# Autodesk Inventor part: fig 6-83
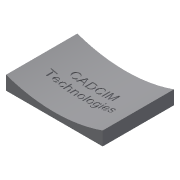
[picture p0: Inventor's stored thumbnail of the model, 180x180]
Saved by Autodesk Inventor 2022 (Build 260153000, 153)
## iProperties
Part Number: fig 6-83
Document SubType Name: Modeling
Created: 2002-12
Designer: deepak
Density: 1 g/cm^3
Material: Generic
Appearance: Default
Control State: 0
Master: False
Checked Out: False
Shininess: 64.0
Length Units: 11269
Angle Units: 11279
Time Units: 11290
Mass Units: 11283
Length Display Precision: 3
Angle Display Precision: 2
Compacted: True
Density: 0.0
Volumn: 0.0
Area: 0.0
PropertySet Name: Model Information
Author: deepak
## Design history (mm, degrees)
sketch "Sketch1"
  geometry: L1 (-39.922, 33.786)-(30.103, 33.786); L2 (30.103, 33.786)-(30.103, -17.894); L3 (30.103, -17.894)-(-39.922, -17.894); L4 (-39.922, -17.894)-(-39.922, 33.786)
  constraints: 8 end point, 2 parallel, 1 horizontal, 1 perpendicular
extrude "Extrusion1" new body sketch "Sketch1" distance "d0" = 10; taper "d1" = 0 deg
workplane "Work Plane1"
sketch "Sketch2"
  geometry: L1 (-37.656, 15.034)-(26.28, 15.034); L2 (26.28, 15.034)-(26.28, 10.168); L3 (26.28, 10.168)-(-37.656, 10.168); L4 (-37.656, 10.168)-(-37.656, 15.034)
  constraints: 2 other
sketch "Sketch3"
  geometry: L1 (70.026, 10)-(0, 10) reference; A1 r 105 centre (35.013, 108.99) between (0, 10) and (70.026, 10)
  constraints: 2 point on circle, 1 centre point
  dimensions: "d5" = 105 radius of A1
extrude "Extrusion2" cut sketch "Sketch3" extent not by distance; stored distance "d3" = 10; taper "d4" = 0 deg
emboss "Emboss4" sketch "Sketch2" dims "d14" = 1, "d15" = 0
body "Solid1"
other parameters: "d2" = 5
